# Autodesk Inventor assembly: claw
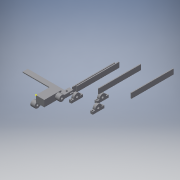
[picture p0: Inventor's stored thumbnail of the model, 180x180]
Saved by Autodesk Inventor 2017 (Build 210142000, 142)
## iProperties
Created: 2017-04
Part Number: claw
Document SubType Name: Assembly
Designer: s4321966
Author: s4321966
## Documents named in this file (5)
- \\puffball.labs.eait.uq.edu.au\s4321966\Documents\metr4810_spool draft\claw.iam
- \\puffball.labs.eait.uq.edu.au\s4321966\Documents\metr4810_spool draft\attachment.ipt
- \\puffball.labs.eait.uq.edu.au\s4321966\Documents\metr4810_spool draft\bar.ipt
- \\puffball.labs.eait.uq.edu.au\s4321966\Documents\metr4810_spool draft\servo attachment.ipt
- \\puffball.labs.eait.uq.edu.au\s4321966\Documents\metr4810_spool draft\servo.ipt
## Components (12 placed, 4 different names)
1. attachment:1
2. bar:1 — Flush:1, Mate:2, Flush:2
3. servo attachment:1 — Mate:1, Tangent:1, Flush:1, Mate:2, Flush:2
4. servo:1 — Mate:1, Tangent:1
5. attachment:2
6. attachment:3
7. servo attachment:2
8. bar:2
9. bar:3
10. bar:4
11. bar:5
12. bar:6
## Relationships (5: Mate 2, Flush 2, Tangent 1)
- Mate:1: servo attachment:1 ↔ servo:1
- Tangent:1: servo attachment:1 ↔ servo:1
- Flush:1: bar:1 ↔ servo attachment:1
- Mate:2: bar:1 ↔ servo attachment:1
- Flush:2: bar:1 ↔ servo attachment:1
